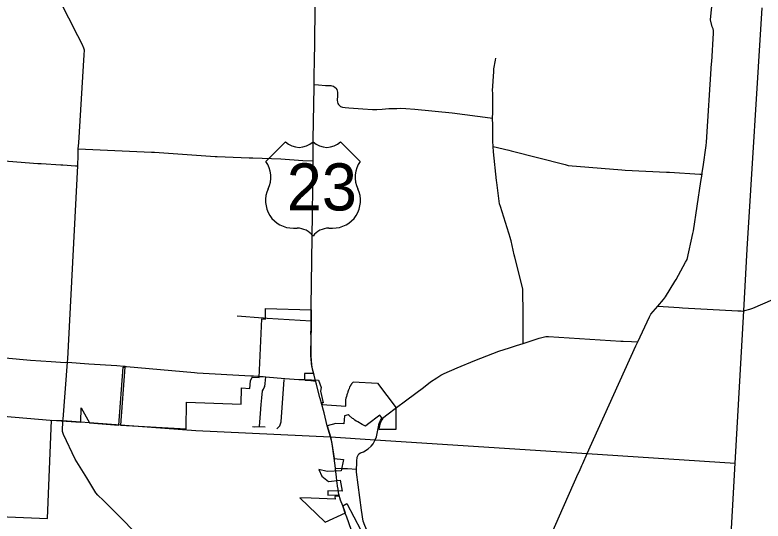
# Model space of a CAD drawing. Extents: x 1729596 to 1925846, y 659247 to 911751.
# Drawn here: x 1799698 to 1821771, y 845758 to 860705 of the extents above; entities that cross this region are included whole.
import ezdxf

# ---------------------------------------------------------------- set-up
doc = ezdxf.new("R2010")
doc.units = 0
for name, color, linetype in [('GM_X_City_Street', 7, 'Continuous'), ('GM_X_Corporation', 7, 'Continuous'), ('GM_X_County_Road', 7, 'Continuous'), ('GM_X_Township', 7, 'Continuous'), ('GM_X_Township_Road', 7, 'Continuous'), ('GM_X_US_Route', 7, 'Continuous'), ('GM_X_US_Shield', 7, 'Continuous')]:
    doc.layers.add(name, color=color, linetype=linetype)

msp = doc.modelspace()

# ---------------------------------------------------------------- linework, layer by layer
at = {"layer": 'GM_X_City_Street'}
for points in [[(1807140, 851748), (1808437, 851668)], [(1806882, 850032), (1807018, 850025), (1807099, 850018), (1807656, 849972), (1808075, 849940), (1808241, 849934), (1808275, 849918), (1808332, 849915), (1808428, 849910), (1808503, 849903), (1808563, 849901)], [(1806917, 848547), (1806947, 848935), (1806958, 849198), (1806978, 849396), (1807000, 849604), (1807027, 849656), (1807053, 849702), (1807070, 849736), (1807078, 849816), (1807099, 850018)], [(1807429, 848485), (1807510, 848566), (1807549, 848686), (1807646, 849939)], [(1810538, 848793), (1810714, 848923), (1810919, 849078)], [(1803391, 844506), (1803386, 844699), (1803411, 844996), (1803417, 845098), (1803416, 845170), (1803320, 845337), (1802730, 845945), (1802308, 846362), (1802144, 846526), (1802086, 846596), (1801814, 847037), (1801477, 847586), (1801128, 848318), (1801102, 848399), (1801113, 848728), (1801117, 848771)], [(1806705, 848555), (1806769, 848544), (1806917, 848547), (1807079, 848543)], [(1809152, 847319), (1809360, 847312)]]:
    msp.add_lwpolyline(points, dxfattribs=at)
at = {"layer": 'GM_X_Corporation'}
msp.add_lwpolyline([(1798053, 845944), (1800661, 845836), (1800775, 848735), (1801643, 848675), (1801648, 849101), (1801894, 848657), (1802762, 848594), (1802886, 850307), (1802936, 850304), (1802812, 848592), (1804746, 848481), (1804763, 849272), (1806371, 849213), (1806387, 849693), (1806631, 849675), (1806647, 849895), (1806700, 850012), (1806903, 849998), (1806985, 851728), (1807088, 851722), (1807090, 852031), (1808433, 851997), (1808431, 850641), (1808436, 850498), (1808449, 850376), (1808470, 850255), (1808504, 850114), (1808243, 850118), (1808241, 849941), (1808654, 849917), (1808737, 849703), (1808710, 849595), (1808790, 849247), (1808740, 849246), (1808759, 849201), (1809456, 849154), (1809458, 849294), (1809459, 849307), (1809460, 849322), (1809461, 849340), (1809462, 849349), (1809463, 849350), (1809464, 849362), (1809467, 849379), (1809470, 849393), (1809472, 849401), (1809475, 849407), (1809476, 849411), (1809477, 849414), (1809480, 849420), (1809484, 849431), (1809486, 849436), (1809491, 849454), (1809497, 849474), (1809502, 849491), (1809511, 849522), (1809527, 849568), (1809534, 849595), (1809537, 849605), (1809541, 849618), (1809544, 849626), (1809546, 849632), (1809551, 849644), (1809560, 849662), (1809565, 849673), (1809578, 849708), (1809583, 849720), (1809588, 849729), (1809593, 849738), (1809606, 849764), (1809611, 849773), (1809615, 849782), (1809621, 849792), (1809623, 849795), (1809628, 849801), (1809637, 849812), (1809641, 849818), (1809647, 849826), (1809654, 849838), (1809659, 849845), (1809666, 849853), (1809681, 849870), (1810394, 849826), (1810945, 849097), (1810937, 849092), (1810939, 848462), (1810440, 848460), (1810456, 848543), (1810463, 848575), (1810469, 848607), (1810479, 848644), (1810492, 848682), (1810515, 848723), (1810542, 848756), (1810552, 848765), (1810465, 848883), (1810105, 848611), (1810039, 848558), (1809945, 848607), (1809817, 848685), (1809792, 848696), (1809763, 848711), (1809726, 848740), (1809697, 848764), (1809685, 848772), (1809662, 848785), (1809560, 848875), (1809530, 848899), (1809421, 848861), (1809398, 848625), (1809168, 848637), (1808914, 848571), (1809012, 848241), (1809052, 848053), (1809117, 847610), (1809395, 847571), (1809325, 847237), (1808906, 847223), (1808660, 847284), (1808750, 847079), (1808950, 846927), (1809294, 846961), (1809355, 846639), (1808928, 846653), (1808933, 846518), (1809251, 846529), (1809259, 846496), (1809133, 846487), (1809149, 846407), (1808433, 846432), (1808107, 846444), (1808850, 845724), (1809453, 845996), (1809370, 846205), (1809495, 846276), (1809904, 845490)], dxfattribs=at)
at = {"layer": 'GM_X_County_Road'}
for points in [[(1801567, 856755), (1801567, 856755), (1801584, 856930), (1801742, 859524), (1801746, 859662), (1801732, 859727), (1801677, 859846), (1801556, 860087), (1800489, 862190), (1800471, 862240), (1800469, 862342), (1800776, 866006), (1800811, 866452), (1800848, 866888), (1800911, 867730), (1800965, 868323), (1801008, 868838), (1801046, 869299), (1801092, 869835), (1801238, 871613)], [(1819979, 856052), (1820004, 856221), (1820093, 856849), (1820106, 856948), (1820253, 859267), (1820256, 859321), (1820308, 860164), (1820312, 860243), (1820295, 860293), (1820272, 860358), (1820219, 860562), (1820238, 860767), (1820341, 861658), (1820408, 862232), (1820454, 862755), (1820524, 864057), (1820528, 864114), (1820480, 864265), (1820462, 864324)], [(1813792, 857659), (1813794, 857827), (1813800, 858197), (1813802, 858295), (1813794, 858400), (1813790, 858459), (1813824, 859039), (1813828, 859109), (1813877, 859368), (1813888, 859424)], [(1808526, 858649), (1808657, 858638), (1808859, 858626), (1809019, 858618), (1809052, 858615), (1809095, 858599), (1809143, 858567), (1809166, 858544), (1809192, 858504), (1809208, 858460), (1809213, 858422), (1809211, 858321), (1809207, 858185), (1809213, 858132), (1809225, 858094), (1809243, 858063), (1809274, 858027), (1809305, 858005), (1809359, 857983), (1809445, 857973), (1809547, 857964), (1809965, 857932), (1810245, 857914), (1810373, 857908), (1810529, 857918), (1810728, 857939), (1810862, 857945), (1810963, 857947), (1811066, 857950), (1811236, 857941), (1811500, 857918), (1812600, 857811), (1813718, 857665), (1813792, 857659)], [(1813810, 856819), (1813800, 856979), (1813794, 857454), (1813792, 857659)], [(1801549, 856244), (1801549, 856244), (1801565, 856560), (1801567, 856755)], [(1801567, 856755), (1803730, 856654), (1803812, 856649), (1805603, 856528), (1805663, 856523)], [(1813810, 856819), (1814272, 856708), (1814342, 856691), (1815928, 856285), (1816023, 856260), (1817602, 856132), (1817706, 856124), (1818919, 856063), (1819010, 856058), (1819906, 856004), (1819971, 856000)], [(1814317, 854102), (1814022, 855049), (1813998, 855126), (1813913, 855754), (1813904, 855818), (1813815, 856658), (1813810, 856819)], [(1801256, 850553), (1801549, 856244)], [(1816452, 847455), (1816586, 847751), (1818021, 850937), (1818081, 851052), (1818426, 851791), (1818463, 851867), (1818600, 852027), (1818667, 852103), (1818835, 852306), (1818895, 852378), (1819166, 852831), (1819205, 852895), (1819487, 853403), (1819531, 853481), (1819699, 854255), (1819715, 854325), (1819940, 855787), (1819971, 856000), (1819979, 856052)], [(1814694, 851004), (1814695, 851266), (1814689, 851950), (1814688, 852505), (1814683, 852620), (1814444, 853547), (1814429, 853618), (1814335, 854030), (1814321, 854092), (1814317, 854102)], [(1810919, 849078), (1811263, 849337), (1811751, 849702), (1811961, 849865), (1812147, 849988), (1812264, 850069), (1812359, 850119), (1812745, 850286), (1813271, 850498), (1813977, 850777), (1814286, 850877), (1814495, 850939), (1814694, 851004)], [(1801117, 848771), (1801250, 850449), (1801256, 850553)], [(1809807, 847663), (1809821, 847704), (1809847, 847739), (1809889, 847777), (1809981, 847807), (1810120, 847890), (1810211, 847966), (1810266, 848041), (1810328, 848152), (1810364, 848247), (1810399, 848390), (1810425, 848536), (1810448, 848647), (1810483, 848724), (1810516, 848777), (1810538, 848793)], [(1809360, 847312), (1809508, 847308), (1809777, 847295), (1809775, 847335), (1809781, 847406), (1809787, 847526), (1809799, 847641), (1809807, 847663)], [(1814101, 842164), (1814760, 843649), (1815210, 844662), (1816320, 847160), (1816351, 847229), (1816426, 847398), (1816452, 847455)]]:
    msp.add_lwpolyline(points, dxfattribs=at)
at = {"layer": 'GM_X_Township'}
for points in [[(1820182, 834021), (1820274, 835623), (1820357, 837080), (1820411, 838018), (1820789, 844650), (1820950, 847472), (1821204, 851968), (1821306, 853784), (1821743, 860915)], [(1794528, 849265), (1800736, 848740), (1801113, 848728), (1805038, 848430), (1809012, 848241), (1810328, 848152), (1816586, 847751), (1820950, 847472)]]:
    msp.add_lwpolyline(points, dxfattribs=at)
at = {"layer": 'GM_X_Township_Road'}
for points in [[(1795090, 856488), (1796016, 856428), (1796449, 856346), (1796551, 856339), (1796604, 856337), (1796665, 856335), (1796771, 856339), (1796829, 856341), (1797357, 856367), (1797448, 856371), (1797816, 856403), (1797914, 856411), (1798495, 856434), (1798591, 856437), (1798633, 856451), (1800371, 856321), (1800474, 856313), (1801054, 856281), (1801112, 856277), (1801481, 856249), (1801549, 856244)], [(1805663, 856523), (1806613, 856487), (1806716, 856483), (1807543, 856452), (1808194, 856410), (1808493, 856392)], [(1821238, 851978), (1821378, 852020), (1821474, 852048), (1822880, 852657), (1822973, 852697), (1822981, 852696), (1823816, 852647), (1823896, 852643), (1826953, 852461), (1827020, 852457), (1827766, 852423)], [(1818667, 852103), (1819299, 852064), (1819393, 852058), (1821027, 851968), (1821128, 851962), (1821176, 851960), (1821204, 851968), (1821237, 851978), (1821238, 851978)], [(1806254, 851821), (1807013, 851757)], [(1794724, 851732), (1794738, 851729), (1794935, 851656), (1795122, 851581), (1795265, 851527), (1796002, 851268), (1796641, 851079), (1797379, 850870), (1797893, 850723), (1797966, 850705), (1798085, 850695), (1798763, 850635), (1800156, 850514), (1800763, 850469), (1801182, 850439), (1801250, 850449)], [(1807013, 851757), (1807030, 851756), (1807140, 851748)], [(1814694, 851004), (1815165, 851158), (1815240, 851182), (1815362, 851206), (1815440, 851209), (1817571, 851075), (1817642, 851071), (1817892, 851059), (1818081, 851052)], [(1801250, 850449), (1801881, 850399), (1802703, 850348), (1802910, 850330), (1802935, 850329)], [(1802935, 850329), (1802961, 850327), (1802988, 850325)], [(1802988, 850325), (1804995, 850144), (1805070, 850138), (1806658, 850048), (1806671, 850048)], [(1806671, 850048), (1806740, 850044), (1806868, 850033), (1806882, 850032)], [(1811145, 843912), (1811099, 843915), (1810940, 843921), (1810776, 843956), (1810680, 844009), (1810636, 844058), (1810436, 844399), (1810264, 844699), (1810200, 844927), (1810124, 845291), (1810078, 845492), (1810023, 845627), (1809977, 845754), (1809919, 846084), (1809777, 847204), (1809777, 847295)]]:
    msp.add_lwpolyline(points, dxfattribs=at)
at = {"layer": 'GM_X_US_Route'}
for points in [[(1808531, 859016), (1808538, 859249), (1808549, 859969), (1808564, 861690), (1808584, 862855), (1808592, 863349), (1808593, 863493)], [(1808510, 857628), (1808515, 857996), (1808526, 858649), (1808531, 858995), (1808531, 859016)], [(1808437, 851954), (1808441, 852097), (1808474, 854817), (1808493, 856392), (1808501, 857014), (1808510, 857555), (1808510, 857628)], [(1808516, 850092), (1808496, 850167), (1808459, 850341), (1808448, 850411), (1808434, 850552), (1808431, 850641), (1808433, 851249), (1808431, 851273), (1808433, 851468), (1808437, 851668), (1808439, 851882), (1808437, 851954)], [(1808563, 849901), (1808563, 849901), (1808522, 850068), (1808516, 850092)], [(1808697, 849401), (1808592, 849800), (1808563, 849901)], [(1808752, 849202), (1808703, 849381), (1808697, 849401)], [(1808821, 848950), (1808803, 849024), (1808752, 849202)], [(1808921, 848545), (1808914, 848571), (1808882, 848700), (1808821, 848950)], [(1809104, 847681), (1809054, 848036), (1809027, 848179), (1809012, 848241), (1809010, 848249), (1808995, 848272), (1808921, 848545)], [(1809164, 847216), (1809152, 847319), (1809114, 847613), (1809104, 847681)], [(1809182, 847063), (1809164, 847216)], [(1809230, 846706), (1809225, 846732), (1809197, 846941), (1809182, 847063)], [(1809249, 846605), (1809230, 846706)], [(1809259, 846555), (1809249, 846605)], [(1809486, 845872), (1809442, 845995), (1809370, 846205), (1809307, 846378), (1809259, 846553), (1809259, 846555)], [(1809906, 844822), (1809859, 844918), (1809769, 845106), (1809684, 845316), (1809486, 845872)]]:
    msp.add_lwpolyline(points, dxfattribs=at)
at = {"layer": 'GM_X_US_Shield'}
for p, q in [((1807680, 856960), (1807100, 856380)), ((1807680, 856960), (1807100, 856380)), ((1809884, 856380), (1809304, 856960)), ((1809884, 856380), (1809304, 856960)), ((1807912, 854408), (1808028, 854408)), ((1807912, 854408), (1808028, 854408)), ((1808956, 854408), (1809072, 854408)), ((1808956, 854408), (1809072, 854408))]:
    msp.add_line(p, q, dxfattribs=at)
for centre, radius, start, end in [((1808086, 857375), 580, 225.573, 314.427), ((1808086, 857375), 580, 225.573, 314.427), ((1808898, 857375), 580, 225.573, 314.427), ((1808898, 857375), 580, 225.573, 314.427), ((1806435, 855915), 812, 334.5471, 35.0009), ((1806435, 855915), 812, 334.5471, 35.0009), ((1810549, 855915), 812, 144.9991, 205.4529), ((1810549, 855915), 812, 144.9991, 205.4529), ((1807903, 855220), 812, 154.8319, 270.6383), ((1807903, 855220), 812, 154.8319, 270.6383), ((1809081, 855220), 812, 269.3617, 25.1681), ((1809081, 855220), 812, 269.3617, 25.1681), ((1808028, 853828), 580, 36.8699, 90), ((1808028, 853828), 580, 36.8699, 90), ((1808956, 853828), 580, 90, 143.1301), ((1808956, 853828), 580, 90, 143.1301)]:
    msp.add_arc(centre, radius, start, end, dxfattribs=at)

# ---------------------------------------------------------------- texts
msp.add_text('23', height=1392.2, dxfattribs=at).set_placement((1807717, 854930))
msp.add_text('23', height=1392.2, dxfattribs=at).set_placement((1807717, 854930))

doc.saveas('drawing.dxf')
